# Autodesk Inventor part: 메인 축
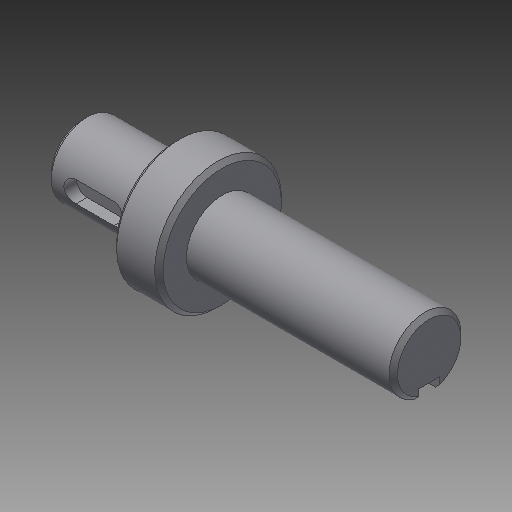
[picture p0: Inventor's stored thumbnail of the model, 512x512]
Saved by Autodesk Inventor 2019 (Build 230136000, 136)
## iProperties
Created: 2014-10
Part Number: 메인 축
Document SubType Name: Modeling
Designer: KYOUNG IL JANG
Density: 7.86 g/cm^3
Mass: 230.24 g
Surface Area: 74.3518 cm^2
Volume: 29.2926 cm^3
Material: 강철, 연강
Appearance: 금속-강(스테인리스, 브러시됨)
Author: SeoGD™ [www.esajin.kr]
Revision Number: 1
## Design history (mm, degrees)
sketch "스케치1"
  geometry: L1 (10.497, -57.5)-(92.497, -57.5); L2 (10.497, -66)-(32.497, -66); L3 (32.497, -72.5)-(46.5, -72.5); L4 (46.5, -66)-(92.497, -66); L5 (92.497, -66)-(92.497, -57.5); L6 (10.497, -66)-(10.497, -57.5); L7 (46.5, -69.749)-(46.5, -45.251) reference; L8 (46.5, -72.5)-(46.5, -66); L9 (32.497, -72.5)-(32.497, -66); L10 (32.497, -35)-(32.497, -80) reference; 2 further points
  constraints: 16 end point, 2 parallel, 2 perpendicular, 2 point on line, 1 collinear, 1 horizontal, 1 midpoint
  dimensions: "d0" = 17 diameter of L4 L1; "d1" = 30 diameter of L3 L1; "d2" = 22 distance of L2.start L2.end; "d5" = 17 diameter of L2 L1; "d19" = 60 distance between parallel lines of L5 L9
revolve "회전1" sketch "스케치1" stored, may be unused: angle "d4" = 90 deg
feature "면 이동2"
chamfer "모따기1" distance "d6" = 1; stored, may be unused: second distance "d7" = 2, angle "d8" = 45 deg
node "작업 평면1"
sketch "스케치2"
  geometry: L1 (-11, -7.5)-(-11, 7.5) reference; L2 (-4.5, 2.5)-(4.5, 2.5); L3 (4.5, -2.5)-(-4.5, -2.5); A1 r 2.5 centre (4.5, 0) between (4.5, -2.5) and (4.5, 2.5); A2 r 2.5 centre (-4.5, 0) between (-4.5, 2.5) and (-4.5, -2.5); 2 further points
  constraints: 4 end point, 4 point on circle, 4 tangent, 2 centre point, 1 horizontal alignment, 1 midpoint, 1 parallel, 1 perpendicular
  dimensions: "d9" = 5 distance between parallel lines of L3 L2; "d10" = 14 dimension on A1 A2; "d11" = 4 distance edge to line of A2 L1
extrude "돌출1" cut sketch "스케치2" distance "d12" = 3; taper "d13" = 0 deg
node "작업 평면2"
sketch "스케치3"
  geometry: L1 (22.998, 7.5)-(22.998, -7.5) reference; L2 (22.998, 2.5)-(7.498, 2.5); L3 (7.498, -2.5)-(22.998, -2.5); A1 r 2.5 centre (7.498, 0) between (7.498, 2.5) and (7.498, -2.5); 2 further points
  constraints: 4 end point, 2 perpendicular, 2 point on circle, 2 point on line, 2 tangent, 1 centre point, 1 horizontal alignment, 1 midpoint
  dimensions: "d14" = 5 distance between parallel lines of L3 L2; "d15" = 18 dimension on A1 L1
extrude "돌출2" cut sketch "스케치3" distance "d16" = 3; taper "d17" = 0 deg
node "솔리드1"
node "참조4"
node "참조5"
